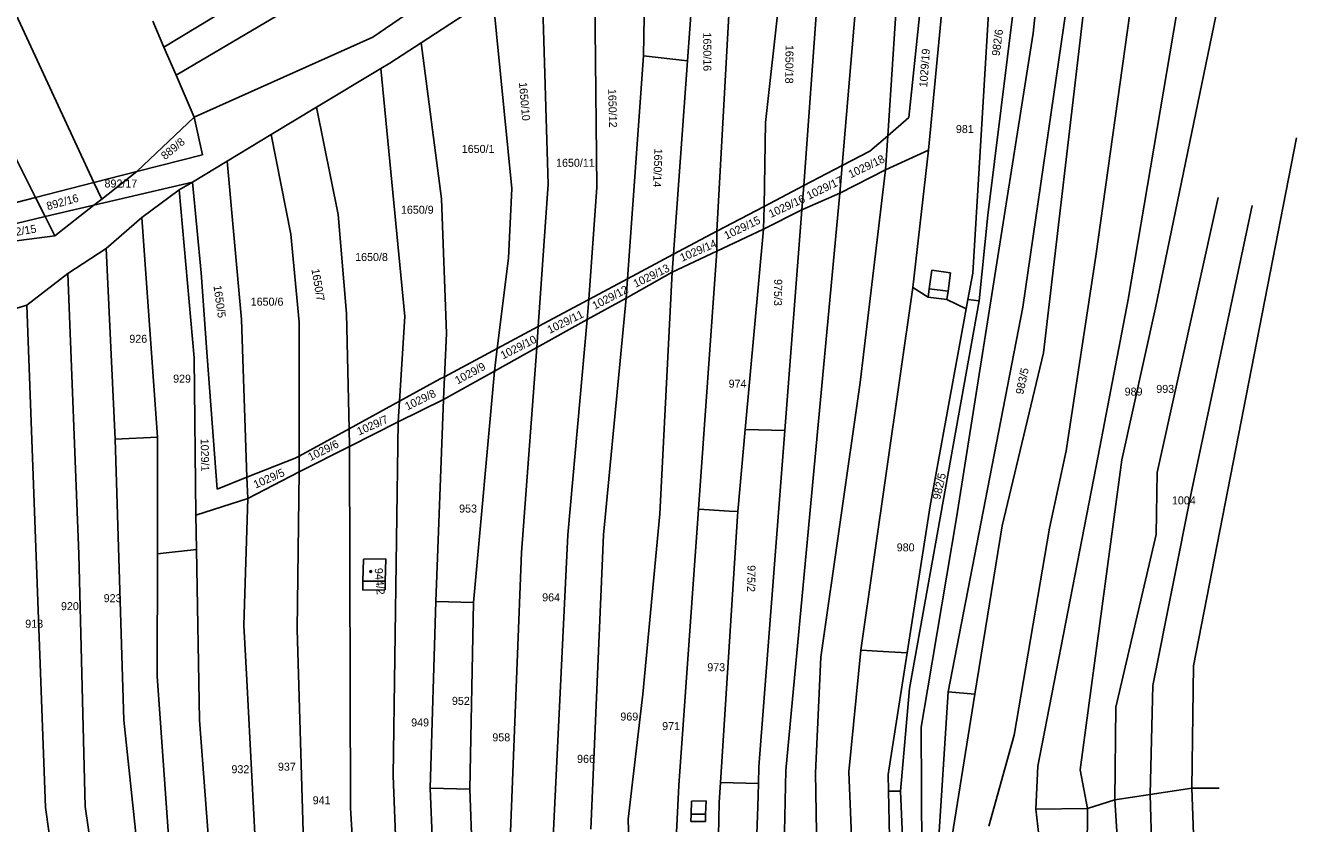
# Model space of a CAD drawing. Extents: x -563148 to -561712, y -1182311 to -1179502.
# Drawn here: x -562330.8 to -562092.6, y -1180362.6 to -1180213.1 of the extents above; entities that cross this region are included whole.
import ezdxf

# ---------------------------------------------------------------- set-up
doc = ezdxf.new("R2010")
doc.units = 0
for name, color, linetype in [('Vrstva 55', 7, 'Continuous'), ('Vrstva 56', 7, 'Continuous'), ('Vrstva 57', 7, 'Continuous')]:
    doc.layers.add(name, color=color, linetype=linetype)

msp = doc.modelspace()

# ---------------------------------------------------------------- linework, layer by layer
at = {"layer": 'Vrstva 55'}
for p, q in [((-562201.22, -1180251.58), (-562196.95, -1180174.45)), ((-562349.32, -1180174.96), (-562317.98, -1180242.5)), ((-562206.71, -1180219.7), (-562203.82, -1180179.65)), ((-562304.86, -1180217.13), (-562260.38, -1180190.17)), ((-562187.44, -1180189.22), (-562192.13, -1180231.23)), ((-562265.71, -1180215.27), (-562233.89, -1180193.41)), ((-562302.57, -1180222.41), (-562256.6, -1180195.12)), ((-562149.32, -1180195.25), (-562153.26, -1180259.47)), ((-562184.93, -1180243.08), (-562181.83, -1180200.05)), ((-562165.22, -1180230.32), (-562161.98, -1180199.25)), ((-562161.54, -1180236.42), (-562158.02, -1180199.17)), ((-562122.21, -1180199.45), (-562130.21, -1180256.28)), ((-562113.05, -1180199.05), (-562124.12, -1180264.41)), ((-562105.11, -1180198.79), (-562118.97, -1180265.98)), ((-562234.09, -1180201.66), (-562232.86, -1180242.82)), ((-562224.1, -1180205.76), (-562223.72, -1180243.34)), ((-562256.67, -1180216.3), (-562243.23, -1180207.59)), ((-562243.23, -1180207.59), (-562239.65, -1180243.6)), ((-562214.98, -1180218.78), (-562214.74, -1180205.96)), ((-562177.75, -1180239.33), (-562175.31, -1180210.62)), ((-562169.19, -1180233.73), (-562167.62, -1180209.83)), ((-562145.51, -1180208.92), (-562150.42, -1180248.59)), ((-562135.67, -1180209.67), (-562143.88, -1180265.84)), ((-562141.36, -1180209.22), (-562141.91, -1180214.53)), ((-562132.46, -1180209.99), (-562139.97, -1180274.38)), ((-562306.96, -1180212.29), (-562304.86, -1180217.13)), ((-562299.17, -1180230.25), (-562265.71, -1180215.27)), ((-562156.32, -1180305.28), (-562141.91, -1180214.53)), ((-562304.86, -1180217.13), (-562302.57, -1180222.41)), ((-562262.55, -1180220.11), (-562256.67, -1180216.3)), ((-562256.67, -1180216.3), (-562252.83, -1180245.56)), ((-562264.21, -1180221.11), (-562262.55, -1180220.11)), ((-562217.99, -1180260.54), (-562214.98, -1180218.78)), ((-562214.98, -1180218.78), (-562206.71, -1180219.7)), ((-562209.33, -1180255.91), (-562206.71, -1180219.7)), ((-562302.57, -1180222.41), (-562299.17, -1180230.25)), ((-562276.24, -1180228.36), (-562264.21, -1180221.11)), ((-562264.21, -1180221.11), (-562259.69, -1180267.57)), ((-562338.59, -1180226.14), (-562328.92, -1180245.29)), ((-562284.78, -1180233.51), (-562276.24, -1180228.36)), ((-562276.24, -1180228.36), (-562272.22, -1180248.5)), ((-562299.17, -1180230.25), (-562309.97, -1180240.46)), ((-562297.62, -1180237.31), (-562299.17, -1180230.25)), ((-562192.38, -1180246.97), (-562192.13, -1180231.23)), ((-562169.19, -1180233.73), (-562165.22, -1180230.32)), ((-562293.03, -1180238.48), (-562284.78, -1180233.51)), ((-562284.78, -1180233.51), (-562281.1, -1180252.16)), ((-562172.55, -1180236.62), (-562169.19, -1180233.73)), ((-562169.61, -1180240.11), (-562169.19, -1180233.73)), ((-562092.55, -1180234.15), (-562111.9, -1180333.04)), ((-562177.75, -1180239.33), (-562172.55, -1180236.62)), ((-562169.61, -1180240.11), (-562161.54, -1180236.42)), ((-562161.54, -1180236.42), (-562164.5, -1180262.15)), ((-562309.97, -1180240.46), (-562297.62, -1180237.31)), ((-562299.53, -1180242.4), (-562293.03, -1180238.48)), ((-562293.03, -1180238.48), (-562290.33, -1180268.15)), ((-562317.98, -1180242.5), (-562309.97, -1180240.46)), ((-562316.52, -1180245.59), (-562309.97, -1180240.46)), ((-562184.93, -1180243.08), (-562177.75, -1180239.33)), ((-562178.19, -1180244.51), (-562177.75, -1180239.33)), ((-562178.19, -1180244.51), (-562169.61, -1180240.11)), ((-562169.61, -1180240.11), (-562174.35, -1180279.94)), ((-562328.92, -1180245.29), (-562317.98, -1180242.5)), ((-562317.98, -1180242.5), (-562316.52, -1180245.59)), ((-562309.02, -1180249.04), (-562302.03, -1180243.89)), ((-562302.03, -1180243.89), (-562299.53, -1180242.4)), ((-562302.03, -1180243.89), (-562299.21, -1180275.34)), ((-562299.53, -1180242.4), (-562297.88, -1180259.44)), ((-562240.3, -1180256.67), (-562239.65, -1180243.6)), ((-562234.7, -1180269.47), (-562232.86, -1180242.82)), ((-562225.24, -1180264.42), (-562223.72, -1180243.34)), ((-562192.38, -1180246.97), (-562184.93, -1180243.08)), ((-562185.26, -1180247.62), (-562184.93, -1180243.08)), ((-562338.7, -1180247.79), (-562328.92, -1180245.29)), ((-562328.92, -1180245.29), (-562327.11, -1180248.88)), ((-562317.98, -1180246.73), (-562316.52, -1180245.59)), ((-562251.92, -1180270.77), (-562252.83, -1180245.56)), ((-562178.19, -1180244.51), (-562188.31, -1180352.65)), ((-562185.26, -1180247.62), (-562178.19, -1180244.51)), ((-562107.26, -1180245.33), (-562118.69, -1180296.83)), ((-562325.3, -1180252.47), (-562317.98, -1180246.73)), ((-562270.66, -1180267.05), (-562272.22, -1180248.5)), ((-562201.22, -1180251.58), (-562192.38, -1180246.97)), ((-562192.45, -1180251.2), (-562192.38, -1180246.97)), ((-562192.45, -1180251.2), (-562185.26, -1180247.62)), ((-562188.48, -1180288.97), (-562185.26, -1180247.62)), ((-562150.42, -1180248.59), (-562152.03, -1180264.63)), ((-562100.87, -1180246.8), (-562112.19, -1180300.06)), ((-562327.11, -1180248.88), (-562325.3, -1180252.47)), ((-562315.72, -1180254.86), (-562309.02, -1180249.04)), ((-562309.02, -1180249.04), (-562306.06, -1180290.18)), ((-562335.46, -1180253.77), (-562325.3, -1180252.47)), ((-562279.53, -1180268.62), (-562281.1, -1180252.16)), ((-562209.33, -1180255.91), (-562201.22, -1180251.58)), ((-562201.23, -1180255.34), (-562192.45, -1180251.2)), ((-562201.23, -1180255.34), (-562201.22, -1180251.58)), ((-562195.89, -1180288.77), (-562192.45, -1180251.2)), ((-562322.89, -1180259.53), (-562315.72, -1180254.86)), ((-562315.72, -1180254.86), (-562314.03, -1180290.58)), ((-562217.99, -1180260.54), (-562209.33, -1180255.91)), ((-562209.57, -1180259.28), (-562201.23, -1180255.34)), ((-562209.57, -1180259.28), (-562209.33, -1180255.91)), ((-562201.23, -1180255.34), (-562204.66, -1180303.66)), ((-562242.37, -1180273.57), (-562240.3, -1180256.67)), ((-562130.21, -1180256.28), (-562135.73, -1180292.73)), ((-562330.59, -1180265.49), (-562322.89, -1180259.53)), ((-562322.89, -1180259.53), (-562320.82, -1180312.08)), ((-562297.88, -1180259.44), (-562296.77, -1180275.05)), ((-562225.24, -1180264.42), (-562217.99, -1180260.54)), ((-562218.25, -1180264.14), (-562209.57, -1180259.28)), ((-562218.25, -1180264.14), (-562217.99, -1180260.54)), ((-562209.57, -1180259.28), (-562211.93, -1180304.57)), ((-562154.17, -1180264.42), (-562153.26, -1180259.47)), ((-562164.5, -1180262.15), (-562174.23, -1180330.11)), ((-562164.5, -1180262.15), (-562161.6, -1180263.94)), ((-562234.7, -1180269.47), (-562225.24, -1180264.42)), ((-562225.51, -1180268.16), (-562218.25, -1180264.14)), ((-562225.51, -1180268.16), (-562225.24, -1180264.42)), ((-562218.25, -1180264.14), (-562222.44, -1180308.51)), ((-562152.03, -1180264.63), (-562165.08, -1180337.24)), ((-562161.6, -1180263.94), (-562158.09, -1180264.41)), ((-562154.49, -1180266.18), (-562158.09, -1180264.41)), ((-562154.49, -1180266.18), (-562154.17, -1180264.42)), ((-562152.03, -1180264.63), (-562154.17, -1180264.42)), ((-562124.12, -1180264.41), (-562129.76, -1180293.66)), ((-562338.04, -1180267.72), (-562330.59, -1180265.49)), ((-562330.59, -1180265.49), (-562327.07, -1180359.58)), ((-562270.66, -1180267.05), (-562270.14, -1180288.61)), ((-562260.69, -1180283.45), (-562259.69, -1180267.57)), ((-562154.49, -1180266.18), (-562161.22, -1180303.03)), ((-562143.88, -1180265.84), (-562157.86, -1180337.87)), ((-562118.97, -1180265.98), (-562125.28, -1180294.44)), ((-562290.33, -1180268.15), (-562289.3, -1180297.71)), ((-562279.53, -1180268.62), (-562279.51, -1180293.73)), ((-562242.37, -1180273.57), (-562234.7, -1180269.47)), ((-562234.97, -1180273.41), (-562225.51, -1180268.16)), ((-562234.97, -1180273.41), (-562234.7, -1180269.47)), ((-562225.51, -1180268.16), (-562229.17, -1180308.48)), ((-562252.29, -1180278.87), (-562251.92, -1180270.77)), ((-562252.29, -1180278.87), (-562242.37, -1180273.57)), ((-562242.89, -1180277.8), (-562234.97, -1180273.41)), ((-562242.89, -1180277.8), (-562242.37, -1180273.57)), ((-562234.97, -1180273.41), (-562237.85, -1180311.78)), ((-562139.97, -1180274.38), (-562147.76, -1180306.79)), ((-562299.21, -1180275.34), (-562298.88, -1180304.79)), ((-562296.77, -1180275.05), (-562294.88, -1180299.91)), ((-562260.69, -1180283.45), (-562253.07, -1180279.29)), ((-562253.07, -1180279.29), (-562252.29, -1180278.87)), ((-562252.48, -1180283.12), (-562242.89, -1180277.8)), ((-562252.48, -1180283.12), (-562252.29, -1180278.87)), ((-562242.89, -1180277.8), (-562246.82, -1180321.17)), ((-562174.35, -1180279.94), (-562181.72, -1180331.37)), ((-562270.14, -1180288.61), (-562260.69, -1180283.45)), ((-562260.93, -1180287.34), (-562252.48, -1180283.12)), ((-562260.93, -1180287.34), (-562260.69, -1180283.45)), ((-562252.48, -1180283.12), (-562253.87, -1180320.95)), ((-562279.51, -1180293.73), (-562270.14, -1180288.61)), ((-562270.14, -1180288.61), (-562270.06, -1180291.92)), ((-562270.06, -1180291.92), (-562260.93, -1180287.34)), ((-562260.93, -1180287.34), (-562261.91, -1180353.6)), ((-562197.3, -1180304.14), (-562195.89, -1180288.77)), ((-562195.89, -1180288.77), (-562188.48, -1180288.97)), ((-562193.37, -1180351.91), (-562188.48, -1180288.97)), ((-562314.03, -1180290.58), (-562306.06, -1180290.18)), ((-562314.03, -1180290.58), (-562312.4, -1180343.22)), ((-562306.06, -1180290.18), (-562306.1, -1180312.07)), ((-562280.24, -1180294.13), (-562279.51, -1180293.73)), ((-562279.51, -1180296.68), (-562270.06, -1180291.92)), ((-562279.51, -1180293.73), (-562279.51, -1180296.68)), ((-562270.06, -1180291.92), (-562269.89, -1180359.62)), ((-562129.76, -1180293.66), (-562141.08, -1180351.82)), ((-562135.73, -1180292.73), (-562138.89, -1180307.24)), ((-562289.3, -1180297.71), (-562280.24, -1180294.13)), ((-562125.28, -1180294.44), (-562133.11, -1180352.51)), ((-562294.88, -1180299.91), (-562289.3, -1180297.71)), ((-562289.3, -1180297.71), (-562289.16, -1180301.68)), ((-562289.16, -1180301.68), (-562279.51, -1180296.68)), ((-562279.51, -1180296.68), (-562279.86, -1180326.23)), ((-562118.69, -1180296.83), (-562118.86, -1180308.42)), ((-562112.19, -1180300.06), (-562119.5, -1180336.7)), ((-562298.88, -1180304.79), (-562289.16, -1180301.68)), ((-562289.16, -1180301.68), (-562289.9, -1180325.42)), ((-562161.22, -1180303.03), (-562165.52, -1180330.57)), ((-562298.88, -1180304.79), (-562298.77, -1180311.2)), ((-562211.93, -1180304.57), (-562215.08, -1180338.34)), ((-562204.66, -1180303.66), (-562208.34, -1180355.41)), ((-562204.66, -1180303.66), (-562202.69, -1180303.79)), ((-562202.69, -1180303.79), (-562198.91, -1180304.04)), ((-562200.54, -1180354.84), (-562197.37, -1180304.97)), ((-562198.91, -1180304.04), (-562197.3, -1180304.14)), ((-562197.3, -1180304.14), (-562197.37, -1180304.97)), ((-562161.72, -1180337.5), (-562156.32, -1180305.28)), ((-562147.76, -1180306.79), (-562152.85, -1180338.35)), ((-562138.89, -1180307.24), (-562145.47, -1180345.98)), ((-562229.17, -1180308.48), (-562231.92, -1180365.13)), ((-562222.44, -1180308.51), (-562224.85, -1180363.63)), ((-562118.86, -1180308.42), (-562126.44, -1180340.78)), ((-562320.82, -1180312.08), (-562319.66, -1180359.35)), ((-562306.1, -1180312.07), (-562306.15, -1180334.96)), ((-562306.1, -1180312.07), (-562304.47, -1180311.88)), ((-562304.47, -1180311.88), (-562300.43, -1180311.4)), ((-562300.43, -1180311.4), (-562298.77, -1180311.2)), ((-562298.77, -1180311.2), (-562298.21, -1180343.18)), ((-562267.56, -1180317.17), (-562267.44, -1180313.03)), ((-562267.44, -1180313.03), (-562263.24, -1180312.99)), ((-562263.24, -1180312.99), (-562263.37, -1180317.15)), ((-562237.85, -1180311.78), (-562239.88, -1180364.12)), ((-562267.61, -1180318.82), (-562267.56, -1180317.17)), ((-562263.37, -1180317.15), (-562263.42, -1180318.79)), ((-562263.42, -1180318.79), (-562267.61, -1180318.82)), ((-562253.87, -1180320.95), (-562254.99, -1180355.92)), ((-562253.87, -1180320.95), (-562246.82, -1180321.17)), ((-562246.82, -1180321.17), (-562247.53, -1180356.09)), ((-562289.9, -1180325.42), (-562289.3, -1180335.71)), ((-562279.86, -1180326.23), (-562278.68, -1180366.24)), ((-562181.72, -1180331.37), (-562182.72, -1180353.05)), ((-562174.23, -1180330.11), (-562176.51, -1180352.89)), ((-562174.23, -1180330.11), (-562169.01, -1180330.39)), ((-562165.52, -1180330.57), (-562169.08, -1180353.36)), ((-562169.01, -1180330.39), (-562165.52, -1180330.57)), ((-562111.9, -1180333.04), (-562112.21, -1180355.93)), ((-562306.15, -1180334.96), (-562303.94, -1180365.74)), ((-562289.3, -1180335.71), (-562287.75, -1180365.66)), ((-562119.5, -1180336.7), (-562119.97, -1180357.13)), ((-562215.08, -1180338.34), (-562217.84, -1180361.73)), ((-562166.79, -1180356.49), (-562165.08, -1180337.24)), ((-562162.89, -1180344.5), (-562161.72, -1180337.5)), ((-562160.69, -1180381.4), (-562157.86, -1180337.87)), ((-562152.85, -1180338.35), (-562158.06, -1180370.64)), ((-562157.86, -1180337.87), (-562152.85, -1180338.35)), ((-562126.44, -1180340.78), (-562126.6, -1180358.14)), ((-562312.4, -1180343.22), (-562306.04, -1180402.33)), ((-562298.21, -1180343.18), (-562295.73, -1180375.88)), ((-562162.89, -1180344.5), (-562162.74, -1180388.34)), ((-562145.47, -1180345.98), (-562150.22, -1180363.08)), ((-562261.91, -1180353.6), (-562261.02, -1180375.62)), ((-562193.43, -1180355.08), (-562193.37, -1180351.91)), ((-562188.31, -1180352.65), (-562188.57, -1180364.08)), ((-562182.72, -1180353.05), (-562182.05, -1180389.7)), ((-562176.51, -1180352.89), (-562174.9, -1180389.94)), ((-562169.08, -1180353.36), (-562169.02, -1180356.48)), ((-562141.08, -1180351.82), (-562141.44, -1180359.85)), ((-562133.11, -1180352.51), (-562131.75, -1180359.71)), ((-562254.99, -1180355.92), (-562253.93, -1180379.39)), ((-562254.99, -1180355.92), (-562247.53, -1180356.09)), ((-562208.34, -1180355.41), (-562209.21, -1180372.58)), ((-562200.78, -1180358.59), (-562200.54, -1180354.84)), ((-562200.54, -1180354.84), (-562193.43, -1180355.08)), ((-562193.51, -1180359.37), (-562193.43, -1180355.08)), ((-562119.97, -1180357.13), (-562112.21, -1180355.93)), ((-562112.21, -1180355.93), (-562111.03, -1180387.77)), ((-562112.21, -1180355.93), (-562107.04, -1180355.93)), ((-562247.53, -1180356.09), (-562246.88, -1180372.72)), ((-562169.02, -1180356.48), (-562168.35, -1180389.4)), ((-562166.79, -1180356.49), (-562169.02, -1180356.48)), ((-562166.79, -1180356.49), (-562164.81, -1180402.42)), ((-562131.75, -1180359.71), (-562126.6, -1180358.14)), ((-562126.6, -1180358.14), (-562119.97, -1180357.13)), ((-562126.6, -1180358.14), (-562125.12, -1180381.59)), ((-562119.97, -1180357.13), (-562119.23, -1180385.38)), ((-562327.07, -1180359.58), (-562323.93, -1180381.08)), ((-562319.66, -1180359.35), (-562316.56, -1180380.65)), ((-562269.89, -1180359.62), (-562267.93, -1180392.1)), ((-562200.78, -1180358.59), (-562201.9, -1180406.19)), ((-562193.51, -1180359.37), (-562194.71, -1180388.25)), ((-562141.44, -1180359.85), (-562131.75, -1180359.71)), ((-562141.44, -1180359.85), (-562135.24, -1180414.04)), ((-562131.75, -1180359.71), (-562131.85, -1180377.27)), ((-562217.84, -1180361.73), (-562216.57, -1180408.2))]:
    msp.add_line(p, q, dxfattribs=at)
at = {"layer": 'Vrstva 56'}
for p, q in [((-562317.98, -1180246.73), (-562299.53, -1180242.4)), ((-562327.11, -1180248.88), (-562317.98, -1180246.73)), ((-562336.87, -1180251.17), (-562327.11, -1180248.88)), ((-562161.4, -1180262.41), (-562160.95, -1180258.94)), ((-562160.95, -1180258.94), (-562157.43, -1180259.4)), ((-562157.43, -1180259.4), (-562157.89, -1180262.87)), ((-562161.6, -1180263.94), (-562161.4, -1180262.41)), ((-562161.4, -1180262.41), (-562157.89, -1180262.87)), ((-562157.89, -1180262.87), (-562158.09, -1180264.41)), ((-562263.37, -1180317.15), (-562267.56, -1180317.17)), ((-562206.06, -1180360.83), (-562205.98, -1180358.34)), ((-562205.98, -1180358.34), (-562203.23, -1180358.29)), ((-562203.23, -1180358.29), (-562203.32, -1180360.79)), ((-562206.1, -1180362.17), (-562206.06, -1180360.83)), ((-562203.36, -1180362.15), (-562206.1, -1180362.17)), ((-562203.32, -1180360.79), (-562206.06, -1180360.83)), ((-562203.32, -1180360.79), (-562203.36, -1180362.15))]:
    msp.add_line(p, q, dxfattribs=at)
at = {"layer": 'Vrstva 57'}
msp.add_circle((-562266.11, -1180315.34), 0.175, dxfattribs=at)

# ---------------------------------------------------------------- texts
for s, rotation, p in [('1650/16', 270.2757, (-562203.78, -1180214.39)), ('982/6', 82.2797, (-562148.23, -1180218.87)), ('1650/18', 269.4289, (-562188.34, -1180216.71)), ('1029/19', 85.9262, (-562161.79, -1180224.71)), ('1650/10', 274.9571, (-562238.32, -1180223.76)), ('1650/12', 271.4879, (-562221.6, -1180224.98)), ('889/8', 39.5987, (-562304.65, -1180238.32)), ('1650/14', 267.828, (-562212.91, -1180236.11)), ('1029/18', 25.6154, (-562176.12, -1180241.72)), ('1029/17', 25.5744, (-562183.97, -1180245.73)), ('892/16', 15.5975, (-562326.64, -1180247.69)), ('1029/16', 25.0398, (-562191.08, -1180249.14)), ('1029/15', 25.807, (-562199.41, -1180253.21)), ('892/15', 9.5543, (-562334.73, -1180252.86)), ('1029/14', 23.5057, (-562207.74, -1180257.35)), ('1029/13', 26.1243, (-562216.43, -1180262.22)), ('1650/7', 279.6394, (-562277.22, -1180258.76)), ('975/3', 269.385, (-562190.46, -1180260.57)), ('1650/5', 277.9868, (-562295.58, -1180261.86)), ('1029/12', 27.5388, (-562224.1, -1180266.35)), ('1029/11', 26.1165, (-562232.55, -1180270.85)), ('1029/10', 27.0647, (-562241.3, -1180275.65)), ('1029/9', 28.4196, (-562249.81, -1180280.33)), ('983/5', 77.571, (-562143.8, -1180282.28)), ('1029/8', 26.0823, (-562259.23, -1180285.2)), ('1029/7', 23.8896, (-562268.29, -1180289.88)), ('1029/1', 271.1633, (-562297.99, -1180290.5)), ('1029/6', 26.3839, (-562277.41, -1180294.69)), ('1029/5', 24.0151, (-562287.68, -1180299.84)), ('982/5', 77.2929, (-562159.36, -1180301.99)), ('944/2', 274.5431, (-562265.36, -1180314.75)), ('975/2', 268.914, (-562195.46, -1180314.15))]:
    msp.add_text(s, height=1.5, rotation=rotation, dxfattribs=at).set_placement(p)
for s, p in [('981', (-562156.41, -1180233.22)), ('1650/1', (-562249.04, -1180236.95)), ('1650/11', (-562231.36, -1180239.55)), ('892/17', (-562316, -1180243.43)), ('1650/9', (-562260.44, -1180248.34)), ('1650/8', (-562269.02, -1180257.2)), ('1650/6', (-562288.6, -1180265.56)), ('926', (-562311.35, -1180272.51)), ('929', (-562303.14, -1180279.98)), ('974', (-562199.01, -1180280.92)), ('989', (-562124.78, -1180282.4)), ('993', (-562118.85, -1180281.9)), ('953', (-562249.53, -1180304.31)), ('1004', (-562115.91, -1180302.78)), ('980', (-562167.5, -1180311.58)), ('923', (-562316.16, -1180321.1)), ('964', (-562233.96, -1180320.94)), ('920', (-562324.16, -1180322.59)), ('918', (-562330.86, -1180325.88)), ('973', (-562203.01, -1180334.03)), ('952', (-562250.88, -1180340.33)), ('949', (-562258.52, -1180344.37)), ('969', (-562219.31, -1180343.27)), ('971', (-562211.47, -1180345.05)), ('958', (-562243.3, -1180347.16)), ('937', (-562283.49, -1180352.66)), ('966', (-562227.42, -1180351.19)), ('932', (-562292.21, -1180353.13)), ('941', (-562276.98, -1180358.95))]:
    msp.add_text(s, height=1.5, dxfattribs=at).set_placement(p)

doc.saveas('drawing.dxf')
